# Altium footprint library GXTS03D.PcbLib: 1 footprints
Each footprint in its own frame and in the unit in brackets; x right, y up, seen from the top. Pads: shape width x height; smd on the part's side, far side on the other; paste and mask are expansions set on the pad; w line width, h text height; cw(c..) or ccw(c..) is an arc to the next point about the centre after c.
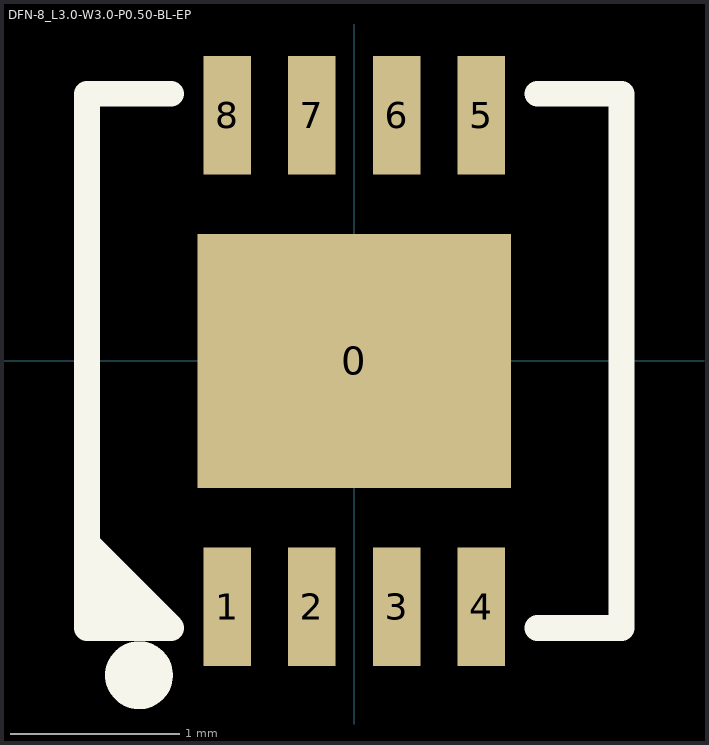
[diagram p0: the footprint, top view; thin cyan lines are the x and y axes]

## DFN-8_L3.0-W3.0-P0.50-BL-EP [mm]
pads (9):
  rect 1.85x1.5 smd: 0(0,0)
  rect 0.28x0.7 smd: 1(-0.75,-1.45) 2(-0.25,-1.45) 3(0.25,-1.45) 4(0.75,-1.45) 5(0.75,1.45) 6(0.25,1.45) 7(-0.25,1.45) 8(-0.75,1.45)
Top Overlay:
  circle w0.2: c-1.27,-1.854 r0.1
  region: -1.08,-1.576 -1.576,-1.576 -1.58,-1.08
  lines w0.152: -1.576,-1.079 -1.08,-1.575 -1.08,-1.576 -1.576,-1.576 -1.576,1.576 -1.08,1.576 ; 1.08,-1.576 1.576,-1.576 1.576,1.576 1.08,1.576
3D body "DFN-8_L3.0-W3.0-P0.50-BL-EP.STEP": height 1.02, standoff 0, extent -1.501,-1.524 1.499,1.496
